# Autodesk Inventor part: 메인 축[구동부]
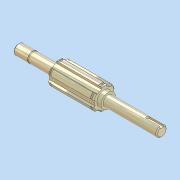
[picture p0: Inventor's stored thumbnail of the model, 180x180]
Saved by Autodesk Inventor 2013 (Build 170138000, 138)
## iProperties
Company: 한국ATC센터
Created: 2012-05
Part Number: 메인 축[구동부]
Document SubType Name: 모델링
Designer: KYOUNG IL JANG
Mass: 168.567 g
Surface Area: 72.5109 cm^2
Volume: 21.4462 cm^3
Density: 7.86 g/cm^3
Material: 강, 연강
변환 표준: STEP AP214IS
파일 이름: C:\Users\SeoGD\Desktop\?쒗뿕\硫붿씤 異?.stp
전처리기: Build: 253, Release: 2010 SP1 - Date: Wed 07/29/2009
전송 단위: 밀리미터
불확실성: 0.01
Author: KYOUNG IL JANG
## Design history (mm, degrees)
sketch "스케치1"
  geometry: L1 (-69.5, 0)-(69.5, 0); L2 (69.5, 0)-(69.5, 5); L3 (69.5, 5)-(55.5, 5); L4 (55.5, 5)-(55.5, 4.8); L5 (55.5, 4.8)-(54.35, 4.8); L6 (54.35, 4.8)-(54.35, 5); L7 (54.35, 5)-(30.5, 5); L8 (30.5, 5)-(30.5, 9); L9 (30.5, 9)-(-13.5, 9); L10 (-13.5, 9)-(-13.5, 7); L11 (-13.5, 7)-(-17.5, 7); L12 (-17.5, 7)-(-17.5, 5); L13 (-17.5, 5)-(-69.5, 5); L14 (-69.5, 5)-(-69.5, 0); 2 further points
  constraints: 28 end point, 9 parallel, 4 collinear, 2 perpendicular, 1 coincident, 1 horizontal, 1 midpoint
  dimensions: "d2" = 1.15 distance between parallel lines of L6 L4; "d3" = 10 diameter of L3 L1; "d4" = 9.6 diameter of L5 L1; "d6" = 44 distance between parallel lines of L10 L8; "d7" = 4 distance between parallel lines of L12 L10; "d8" = 14 diameter of L11 L1; "d9" = 18 diameter of L9 L1; "d33" = 52 distance from line of L12.end L14; "d37" = 39 distance between parallel lines of L8 L2; "d38" = 14 distance between parallel lines of L2 L4
revolve "회전1" sketch "스케치1" stored, may be unused: angle "d10" = 90 deg
sketch "스케치2"
  geometry: L1 (2.5, 10.712)-(2.5, 8.646); L2 (-2.5, 10.712)-(-2.5, 8.646); A1 r 9 centre (0, 0) between (2.5, 8.646) and (-2.5, 8.646) reference; A2 r 11 centre (0, 0) between (2.5, 10.712) and (-2.5, 10.712); 1 further point
  constraints: 4 end point, 4 point on circle, 2 parallel, 1 centre point, 1 coincident, 1 vertical
  dimensions: "d11" = 22 diameter of A2; "d12" = 5 distance between parallel lines of L1 L2
extrude "돌출1" join sketch "스케치2" stored distance "d13" = 10; taper "d14" = 0 deg
chamfer "모따기1" distance "d15" = 1; stored, may be unused: second distance "d16" = 2, angle "d17" = 45 deg
node "작업 평면1"
node "작업 평면2"
sketch "스케치3"
  geometry: L1 (2.5, 10.712)-(2.5, 10.198); L2 (-2.5, 10.712)-(-2.5, 10.198); A1 r 11 centre (0, 0) between (2.5, 10.712) and (-2.5, 10.712) reference; A2 r 10.5 centre (0, 0) between (2.5, 10.198) and (-2.5, 10.198); 1 further point
  constraints: 4 end point, 2 point on circle, 1 centre point, 1 coincident, 1 parallel, 1 vertical
  dimensions: "d19" = 21 diameter of A2
extrude "돌출2" cut sketch "스케치3" distance "d20" = 1.35; taper "d21" = 0 deg
node "작업 평면3"
sketch "스케치4"
  geometry: L1 (-26, -5)-(-26, 5) reference; L2 (-26, 1.5)-(-12.5, 1.5); L3 (-12.5, -1.5)-(-26, -1.5); A1 r 1.5 centre (-12.5, 0) between (-12.5, -1.5) and (-12.5, 1.5); 2 further points
  constraints: 4 end point, 2 perpendicular, 2 point on circle, 2 point on line, 2 tangent, 1 centre point, 1 horizontal alignment, 1 midpoint
  dimensions: "d25" = 3 distance between parallel lines of L3 L2; "d26" = 15 dimension on A1 L1
extrude "돌출3" cut sketch "스케치4" distance "d27" = 1.8; taper "d28" = 0 deg
chamfer "모따기2" distance "d29" = 1; stored, may be unused: second distance "d30" = 2, angle "d31" = 45 deg
node "솔리드1"
node "솔리드 본체"
node "곡면 본체"
mirror "대칭1"
pattern_circular "원형 패턴1" dims "d23" = 360 deg
node "솔리드2"
other parameters: "d18" = -1.65
